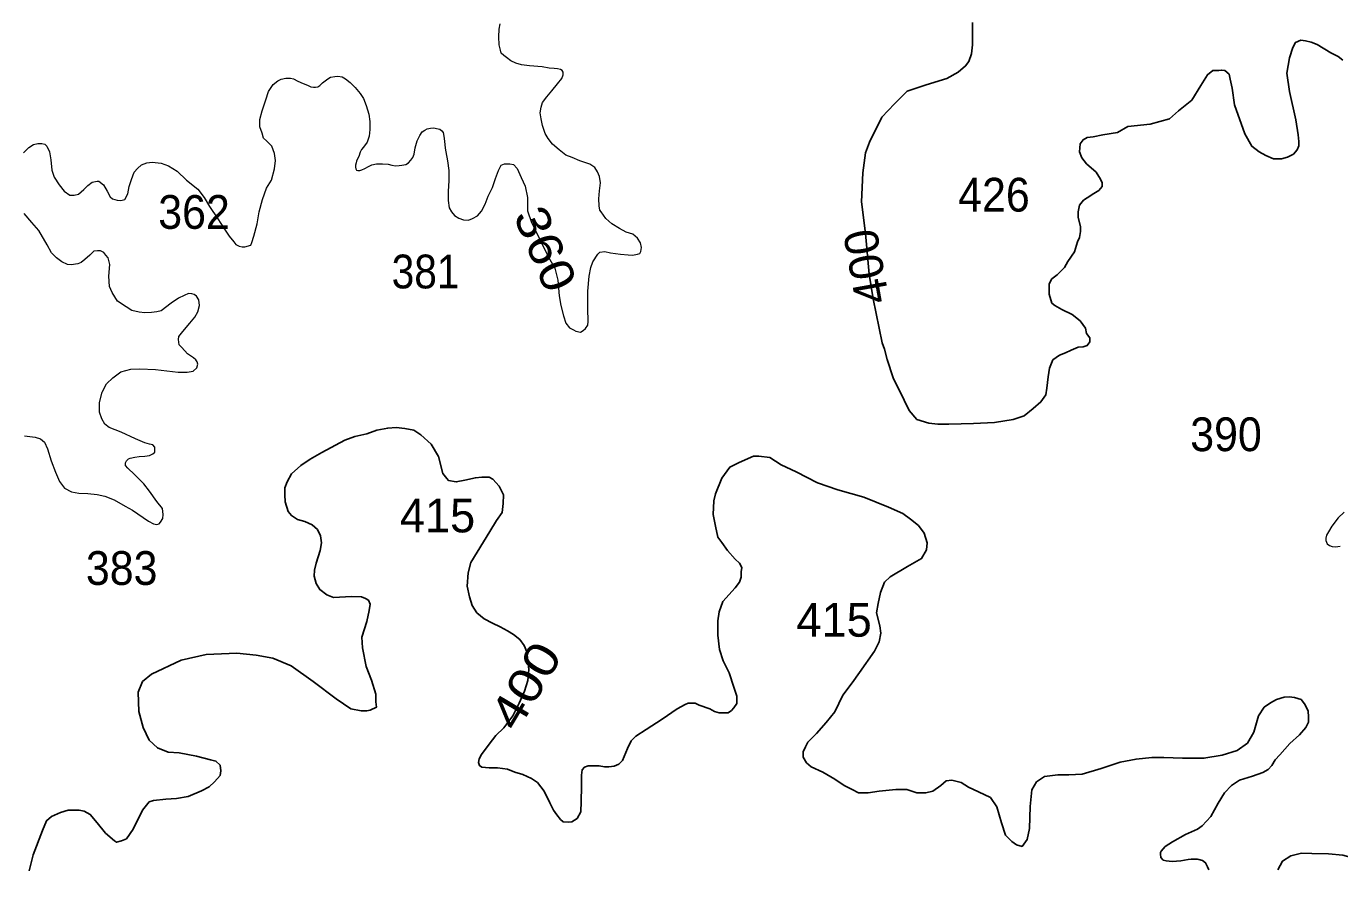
# Model space of a CAD drawing. Extents: x 445.4 to 500, y 8728.7 to 8784.
# Drawn here: x 472.73 to 478.95, y 8728.71 to 8732.71 of the extents above; entities that cross this region are included whole.
import ezdxf
from ezdxf.enums import TextEntityAlignment as Align

# ---------------------------------------------------------------- set-up
doc = ezdxf.new("R2010")
doc.units = 0
doc.header["$LTSCALE"] = 0.064
doc.layers.add('1', color=7, linetype='Continuous', lineweight=25)
doc.layers.add('2', color=7, linetype='Continuous', lineweight=13)
doc.layers.add('21', color=7, linetype='Continuous')
doc.layers.add('61', color=7, linetype='Continuous')

msp = doc.modelspace()

# ---------------------------------------------------------------- linework, layer by layer
at = {"layer": '1'}
for points in [[(476.7866, 8731.2088), (476.7434, 8731.4167), (476.7247, 8731.5347), (476.7078, 8731.7273), (476.689, 8731.8772), (476.6946, 8732.0139), (476.7078, 8732.1091), (476.7266, 8732.1597), (476.7847, 8732.2777), (476.8448, 8732.3414), (476.9049, 8732.4013), (476.995, 8732.4313), (477.0925, 8732.4613), (477.147, 8732.4912), (477.1813, 8732.5206), (477.1963, 8732.5412), (477.2094, 8732.5787), (477.215, 8732.6199), (477.215, 8732.7267)], [(478.9125, 8732.5825), (478.8469, 8732.6224), (478.8184, 8732.6338), (478.7927, 8732.6395), (478.7699, 8732.6423), (478.7442, 8732.6309), (478.7328, 8732.6081), (478.7157, 8732.5597), (478.7043, 8732.4857), (478.7157, 8732.4003), (478.7464, 8732.2651), (478.7578, 8732.1939), (478.7607, 8732.1626), (478.7607, 8732.1426), (478.7521, 8732.1227), (478.735, 8732.1028), (478.7065, 8732.0885), (478.6779, 8732.08), (478.6409, 8732.08), (478.6038, 8732.0971), (478.5724, 8732.1142), (478.5381, 8732.1398), (478.5039, 8732.1996), (478.4554, 8732.3363), (478.444, 8732.416), (478.4354, 8732.4587), (478.4297, 8732.4815), (478.4097, 8732.4986), (478.3955, 8732.5014), (478.3812, 8732.4986), (478.3527, 8732.4986), (478.327, 8732.4787), (478.2956, 8732.4274), (478.2528, 8732.3591), (478.1901, 8732.3078), (478.1473, 8732.2708), (478.056, 8732.2452), (477.9504, 8732.2338), (477.9019, 8732.2053), (477.8321, 8732.1938), (477.7865, 8732.1852), (477.7579, 8732.1824), (477.738, 8732.171), (477.7237, 8732.1511), (477.7208, 8732.114), (477.7323, 8732.0856), (477.7551, 8732.0571), (477.8007, 8732.0172), (477.8207, 8731.984), (477.8292, 8731.9669), (477.8292, 8731.9498), (477.8121, 8731.9299), (477.7893, 8731.9156), (477.7579, 8731.8957), (477.7408, 8731.8843), (477.7208, 8731.8615), (477.7151, 8731.8302), (477.7151, 8731.8046), (477.7265, 8731.759), (477.7265, 8731.7362), (477.7208, 8731.7078), (477.7122, 8731.6878), (477.698, 8731.6394), (477.6666, 8731.5939), (477.6495, 8731.5654), (477.6152, 8731.5312), (477.5896, 8731.5113), (477.5781, 8731.4885), (477.5781, 8731.4401), (477.5896, 8731.3974), (477.6038, 8731.386), (477.6381, 8731.366), (477.6866, 8731.3433), (477.7238, 8731.3131), (477.7495, 8731.2789), (477.7552, 8731.2533), (477.7695, 8731.2333), (477.7695, 8731.2134), (477.758, 8731.1963), (477.7381, 8731.1906), (477.7152, 8731.1878), (477.681, 8731.1735), (477.6553, 8731.1621), (477.6268, 8731.1508), (477.5954, 8731.128), (477.5783, 8731.0881), (477.5726, 8731.0482), (477.5669, 8730.9941), (477.5612, 8730.9628), (477.5384, 8730.9286), (477.5013, 8730.8973), (477.4585, 8730.8631), (477.4071, 8730.8461), (477.3187, 8730.8318), (477.2188, 8730.8261), (477.1018, 8730.8233), (477.0505, 8730.8233), (477.0077, 8730.829), (476.9506, 8730.8461), (476.9135, 8730.8888), (476.8907, 8730.9372)], [(478.9696, 8732.5483), (478.9468, 8732.5654), (478.9125, 8732.5825)], [(476.8907, 8730.9372), (476.8379, 8731.0423), (476.8093, 8731.1306), (476.7979, 8731.179), (476.7866, 8731.2088)], [(472.7448, 8728.708), (472.7639, 8728.784), (472.8067, 8728.8989), (472.8264, 8728.9449), (472.8494, 8728.9646), (472.8922, 8728.9843), (472.9284, 8728.9942), (472.9811, 8728.9942), (473.0041, 8728.9909), (473.0337, 8728.9745), (473.0666, 8728.9351), (473.1061, 8728.8858), (473.1489, 8728.8497), (473.1587, 8728.8431), (473.1818, 8728.8497), (473.2048, 8728.8595), (473.2377, 8728.9055), (473.2805, 8728.9942), (473.3134, 8729.0336), (473.3331, 8729.0402), (473.3924, 8729.0467), (473.4417, 8729.05), (473.4976, 8729.0599), (473.5602, 8729.0861), (473.5964, 8729.1058), (473.6227, 8729.1288), (473.649, 8729.1584), (473.6523, 8729.1814), (473.649, 8729.2076), (473.6293, 8729.2274), (473.6029, 8729.2339), (473.5371, 8729.2503), (473.4549, 8729.2668), (473.4022, 8729.27), (473.3529, 8729.2898), (473.3134, 8729.3259), (473.2843, 8729.387), (473.2645, 8729.4625), (473.2612, 8729.5544), (473.281, 8729.6037), (473.3238, 8729.6398), (473.4652, 8729.7055), (473.5837, 8729.7318), (473.7285, 8729.7384), (473.8206, 8729.7285), (473.8996, 8729.7154), (473.9851, 8729.6792), (474.0904, 8729.6037), (474.199, 8729.5216), (474.2681, 8729.4756), (474.3175, 8729.4658), (474.3438, 8729.4658), (474.3602, 8729.4691), (474.3899, 8729.4822), (474.3866, 8729.5085), (474.3866, 8729.5446), (474.3668, 8729.6103), (474.3405, 8729.676), (474.324, 8729.7646), (474.3208, 8729.8139), (474.3438, 8729.8894), (474.3548, 8729.9405), (474.3596, 8729.9709), (474.3516, 8729.9895), (474.3383, 8729.9975), (474.3196, 8730.0055), (474.2715, 8730.0068), (474.1861, 8730.0029), (474.1554, 8730.0148), (474.122, 8730.0402), (474.1046, 8730.0681), (474.0953, 8730.1028), (474.0966, 8730.1321), (474.1046, 8730.1654), (474.1232, 8730.225), (474.1299, 8730.261), (474.1246, 8730.2943), (474.1099, 8730.325), (474.0859, 8730.3463), (474.0512, 8730.3623), (474.0151, 8730.3716), (473.9871, 8730.3903), (473.971, 8730.4103), (473.9574, 8730.4562), (473.956, 8730.4882), (473.956, 8730.5215), (473.9667, 8730.5508), (473.9867, 8730.5881), (474.0321, 8730.6281), (474.0762, 8730.6574), (474.1309, 8730.6894), (474.2394, 8730.7476), (474.2875, 8730.7649), (474.3449, 8730.7783), (474.3916, 8730.7956), (474.4437, 8730.8049), (474.4838, 8730.8076), (474.5238, 8730.8036), (474.5665, 8730.7956), (474.5999, 8730.7729), (474.6493, 8730.729)], [(474.6493, 8730.729), (474.684, 8730.6703), (474.704, 8730.5904), (474.7241, 8730.5654), (474.7306, 8730.5567), (474.7676, 8730.5502), (474.8089, 8730.5588), (474.859, 8730.5697), (474.8894, 8730.5719), (474.9243, 8730.5719), (474.9417, 8730.5632), (474.9721, 8730.5306), (474.9917, 8730.4893), (474.9896, 8730.4481), (474.9852, 8730.4046), (474.9591, 8730.3677), (474.9264, 8730.3156), (474.837, 8730.1689), (474.824, 8730.119), (474.8196, 8730.056), (474.8305, 8730.006), (474.8436, 8729.9648), (474.8653, 8729.93), (474.9003, 8729.9009), (474.9394, 8729.8813), (474.9764, 8729.864), (475.0113, 8729.8444), (475.0395, 8729.827), (475.07, 8729.8031), (475.0896, 8729.7749), (475.1027, 8729.7445), (475.1115, 8729.6608), (475.1071, 8729.6087), (475.0919, 8729.5588), (475.0658, 8729.5023), (475.0353, 8729.4415), (474.994, 8729.385), (474.9548, 8729.3481), (474.9243, 8729.3068), (474.8871, 8729.2579), (474.8762, 8729.2384), (474.874, 8729.221), (474.8784, 8729.2058), (474.8893, 8729.1993), (474.9241, 8729.1949), (474.9633, 8729.1949), (475.0111, 8729.1884), (475.046, 8729.1754), (475.083, 8729.1645), (475.1243, 8729.145), (475.1526, 8729.1254), (475.1852, 8729.0842), (475.2114, 8729.0299), (475.2288, 8728.9951), (475.2446, 8728.9724), (475.262, 8728.9507), (475.2751, 8728.9398), (475.299, 8728.9376), (475.3164, 8728.9398), (475.3403, 8728.955), (475.3578, 8728.9876), (475.3599, 8729.0354), (475.3621, 8729.107), (475.3621, 8729.1613), (475.3643, 8729.1852), (475.3752, 8729.1983), (475.3926, 8729.2048), (475.4209, 8729.2048), (475.4448, 8729.2048), (475.4709, 8729.2004), (475.4905, 8729.2004), (475.5166, 8729.2026), (475.5384, 8729.2135), (475.5558, 8729.2309), (475.5797, 8729.2873), (475.5975, 8729.3235), (475.6193, 8729.3453), (475.6672, 8729.3778), (475.7433, 8729.4256), (475.8152, 8729.4756), (475.8521, 8729.4951), (475.8674, 8729.5017), (475.9, 8729.5017), (475.9196, 8729.493), (475.9697, 8729.4756), (475.9914, 8729.4626), (476.0132, 8729.456), (476.0371, 8729.456), (476.0567, 8729.456), (476.0719, 8729.4669), (476.0828, 8729.4799), (476.0981, 8729.4995), (476.0981, 8729.5342), (476.0828, 8729.5777), (476.0611, 8729.645), (476.0331, 8729.7025), (476.0157, 8729.7568), (476.007, 8729.8241), (476.007, 8729.8915), (476.0135, 8729.9349), (476.0309, 8729.9827)], [(476.0309, 8729.9827), (476.0897, 8730.0479), (476.1097, 8730.0755), (476.1184, 8730.0994), (476.1184, 8730.1233), (476.1206, 8730.145), (476.1097, 8730.1645), (476.0901, 8730.1841), (476.0531, 8730.2253), (476.027, 8730.2623), (476.0074, 8730.2883), (475.9963, 8730.34), (475.9851, 8730.3961), (475.9888, 8730.4596), (475.9963, 8730.4932), (476.0263, 8730.5679), (476.0637, 8730.6202), (476.1086, 8730.6426), (476.176, 8730.6725), (476.2022, 8730.6725), (476.2546, 8730.665), (476.307, 8730.6314), (476.3781, 8730.5978), (476.4792, 8730.5455), (476.5765, 8730.5119), (476.7, 8730.4782), (476.8161, 8730.4297), (476.8834, 8730.3998), (476.9209, 8730.3736), (476.9583, 8730.3438), (476.9845, 8730.3064), (476.9995, 8730.2616), (476.9957, 8730.2279), (476.9733, 8730.1868), (476.9059, 8730.1495), (476.8235, 8730.1009), (476.7973, 8730.0748), (476.7786, 8730.0262), (476.7674, 8729.9739), (476.7599, 8729.9291), (476.7754, 8729.8678), (476.7791, 8729.8342), (476.7717, 8729.7931), (476.7492, 8729.7482), (476.6781, 8729.6474), (476.6444, 8729.5988), (476.5995, 8729.539), (476.562, 8729.4606), (476.5208, 8729.41), (476.4758, 8729.3577), (476.4347, 8729.3166), (476.4234, 8729.2942), (476.4122, 8729.2717), (476.4122, 8729.2456), (476.4272, 8729.2194), (476.4496, 8729.2008), (476.5058, 8729.1746), (476.5619, 8729.141), (476.6069, 8729.1111), (476.6443, 8729.0924), (476.6742, 8729.0775), (476.7191, 8729.0775), (476.7715, 8729.0849), (476.8502, 8729.0924), (476.9026, 8729.0924), (476.9512, 8729.0775), (476.9924, 8729.0775), (477.0261, 8729.0849), (477.0635, 8729.1111), (477.0897, 8729.1335), (477.1159, 8729.1373), (477.1608, 8729.126), (477.1945, 8729.1036), (477.2432, 8729.0812), (477.2993, 8729.0551), (477.3293, 8729.0102), (477.3517, 8728.9355), (477.3704, 8728.8757), (477.4004, 8728.8459), (477.4228, 8728.8309), (477.449, 8728.8234), (477.4725, 8728.856), (477.4838, 8728.9083), (477.4875, 8729.0129), (477.495, 8729.0913), (477.5175, 8729.1287), (477.5549, 8729.1548), (477.6185, 8729.1623), (477.6709, 8729.1623), (477.7346, 8729.166), (477.8244, 8729.1922), (477.9142, 8729.2221), (477.9891, 8729.237), (478.0639, 8729.2445), (478.1201, 8729.2445), (478.2099, 8729.2408), (478.311, 8729.2408), (478.3971, 8729.2557), (478.4682, 8729.2781), (478.5169, 8729.3117), (478.5468, 8729.364)], [(478.5468, 8729.364), (478.5693, 8729.4425), (478.5964, 8729.4823), (478.6258, 8729.5032), (478.6552, 8729.5186), (478.6916, 8729.5297), (478.714, 8729.5325), (478.7406, 8729.5283), (478.7713, 8729.5186), (478.7881, 8729.499), (478.8049, 8729.4655), (478.8063, 8729.4362), (478.8063, 8729.4124), (478.7937, 8729.3859), (478.7643, 8729.3524), (478.7182, 8729.3105), (478.6706, 8729.2574), (478.6492, 8729.2334), (478.6321, 8729.2068), (478.615, 8729.1878), (478.5902, 8729.1726), (478.5408, 8729.1556), (478.4799, 8729.1366), (478.4418, 8729.1119), (478.4076, 8729.0777), (478.379, 8729.0283), (478.3429, 8728.9656), (478.3029, 8728.9201), (478.2801, 8728.9049), (478.223, 8728.8802), (478.1621, 8728.8441), (478.1277, 8728.8222), (478.1086, 8728.8), (478.1055, 8728.7937), (478.1055, 8728.7857), (478.1071, 8728.7699), (478.1182, 8728.7588), (478.1325, 8728.7556), (478.1611, 8728.7524), (478.1801, 8728.754), (478.2008, 8728.7556), (478.2357, 8728.7604), (478.2516, 8728.7635), (478.2675, 8728.7635), (478.2802, 8728.762), (478.2865, 8728.7604), (478.304, 8728.7572), (478.3183, 8728.7461), (478.3278, 8728.7271), (478.3335, 8728.7123)], [(478.6614, 8728.7126), (478.6828, 8728.7538), (478.7229, 8728.7791), (478.7734, 8728.7917), (478.8218, 8728.7896), (478.9019, 8728.7875), (478.9692, 8728.7812), (479.0345, 8728.7644), (479.0851, 8728.7433), (479.1335, 8728.716), (479.1368, 8728.7129)]]:
    msp.add_lwpolyline(points, dxfattribs=at)
at = {"layer": '2'}
for points in [[(474.9542, 8731.9877), (474.9686, 8732.0248), (474.9801, 8732.0499), (474.997, 8732.0562), (475.0224, 8732.0562), (475.0394, 8732.0541), (475.0563, 8732.0351), (475.0754, 8731.9929), (475.0944, 8731.9506), (475.105, 8731.8978), (475.105, 8731.8344), (475.1244, 8731.7782), (475.1476, 8731.7317), (475.1751, 8731.6747), (475.2111, 8731.6029), (475.2344, 8731.5627), (475.2492, 8731.5057), (475.2556, 8731.4318), (475.2641, 8731.386), (475.2768, 8731.3374), (475.2874, 8731.3015), (475.3043, 8731.2804), (475.3234, 8731.2698), (475.3339, 8731.2635), (475.3572, 8731.2593), (475.3699, 8731.2677), (475.3805, 8731.2762), (475.3911, 8731.2931), (475.3932, 8731.31), (475.3911, 8731.3712), (475.3911, 8731.4536), (475.3974, 8731.5254), (475.4059, 8731.5656), (475.4144, 8731.593), (475.4381, 8731.6283), (475.4487, 8731.6388), (475.472, 8731.6409), (475.4995, 8731.6346), (475.5461, 8731.6283), (475.5821, 8731.6261), (475.6032, 8731.624), (475.6265, 8731.6283), (475.6371, 8731.6325), (475.6434, 8731.6409), (475.6456, 8731.6599), (475.6413, 8731.6832), (475.6265, 8731.7043), (475.6053, 8731.7233), (475.5736, 8731.7339), (475.5419, 8731.7508), (475.5059, 8731.7719), (475.4762, 8731.7972), (475.4551, 8731.8289), (475.4487, 8731.8374), (475.4444, 8731.8582), (475.443, 8731.8916), (475.447, 8731.929), (475.4511, 8731.9664), (475.447, 8731.9972), (475.4377, 8732.0186), (475.4243, 8732.0399), (475.4015, 8732.0546), (475.3533, 8732.0707), (475.3172, 8732.0867), (475.2877, 8732.0974), (475.2556, 8732.1228), (475.2248, 8732.1495), (475.2034, 8732.1776), (475.19, 8732.2003), (475.1764, 8732.2385), (475.1697, 8732.2693), (475.1657, 8732.2987), (475.1697, 8732.3254), (475.1764, 8732.3481), (475.1965, 8732.3749), (475.2206, 8732.4029), (475.2474, 8732.4363), (475.2688, 8732.4617), (475.2746, 8732.4778), (475.2739, 8732.491), (475.2695, 8732.4983), (475.2614, 8732.5035), (475.2481, 8732.5071), (475.2327, 8732.5086), (475.2077, 8732.5108), (475.1745, 8732.5167), (475.115, 8732.5204), (475.0767, 8732.5262), (475.0502, 8732.5343), (475.0267, 8732.5446), (475.0068, 8732.56), (474.9928, 8732.5696), (474.9801, 8732.581), (474.9772, 8732.595), (474.9706, 8732.6214), (474.9691, 8732.6581), (474.9713, 8732.6941), (474.9764, 8732.7198)], [(473.8544, 8732.1779), (473.8478, 8732.202), (473.8378, 8732.2321), (473.8378, 8732.2671), (473.8478, 8732.3072), (473.8654, 8732.3599), (473.878, 8732.4), (473.9005, 8732.4325), (473.9231, 8732.4501), (473.9377, 8732.4585), (473.9608, 8732.4626), (473.9823, 8732.4626), (473.9972, 8732.4593), (474.017, 8732.4486), (474.0418, 8732.4378), (474.0625, 8732.4296), (474.0782, 8732.4222), (474.0914, 8732.4197), (474.1005, 8732.4205), (474.112, 8732.4213), (474.1219, 8732.4279), (474.1343, 8732.4411), (474.1591, 8732.4601), (474.1723, 8732.4667), (474.193, 8732.47), (474.207, 8732.4717), (474.2269, 8732.4684), (474.2426, 8732.4601), (474.2649, 8732.4428), (474.2897, 8732.4181), (474.312, 8732.3908), (474.3285, 8732.3661), (474.3409, 8732.3339), (474.3539, 8732.2921), (474.3589, 8732.2573), (474.3589, 8732.2192), (474.3556, 8732.1877), (474.3456, 8732.1595), (474.329, 8732.1363), (474.3184, 8732.1241), (474.3126, 8732.1115), (474.3067, 8732.0922), (474.2999, 8732.0805), (474.2959, 8732.0701), (474.2941, 8732.0611), (474.2905, 8732.0508), (474.2905, 8732.0413), (474.2914, 8732.0336), (474.2954, 8732.0273), (474.3017, 8732.0255), (474.3112, 8732.0255), (474.3202, 8732.0287), (474.3351, 8732.0354), (474.3514, 8732.0449), (474.3676, 8732.0517), (474.3897, 8732.0575), (474.4185, 8732.0571), (474.4456, 8732.0548), (474.4627, 8732.0508), (474.4808, 8732.0481), (474.497, 8732.0494), (474.5096, 8732.0499), (474.529, 8732.0544), (474.5412, 8732.062), (474.5527, 8732.0735), (474.5626, 8732.0872), (474.5687, 8732.1024), (474.5733, 8732.1322), (474.5832, 8732.1658), (474.5955, 8732.1917), (474.6062, 8732.2077), (474.6192, 8732.2166), (474.6307, 8732.2219), (474.6452, 8732.2265), (474.6613, 8732.2272), (474.675, 8732.225), (474.6896, 8732.2211), (474.7003, 8732.2135), (474.7064, 8732.2051), (474.7094, 8732.1883), (474.7125, 8732.1639), (474.7156, 8732.1311), (474.7186, 8732.1136), (474.7264, 8732.0711), (474.7336, 8732.0248), (474.7321, 8731.9762), (474.7293, 8731.9276), (474.7293, 8731.8833), (474.735, 8731.8489), (474.745, 8731.8289), (474.7594, 8731.8118), (474.7809, 8731.7989), (474.8024, 8731.7917), (474.8253, 8731.7903), (474.8453, 8731.7975), (474.8683, 8731.8103), (474.8869, 8731.8332), (474.9055, 8731.8661), (474.9199, 8731.9033), (474.9399, 8731.9448), (474.9542, 8731.9877)], [(472.7176, 8732.1087), (472.7427, 8732.1338), (472.7645, 8732.1488), (472.7846, 8732.1538), (472.8046, 8732.1538), (472.818, 8732.1505), (472.8281, 8732.1405), (472.8398, 8732.1137), (472.8465, 8732.0753), (472.8515, 8732.0269), (472.8632, 8731.9934), (472.8867, 8731.9567), (472.9101, 8731.9266), (472.9369, 8731.9082), (472.957, 8731.9082), (472.9787, 8731.9133), (473.0038, 8731.935), (473.0222, 8731.955), (473.0423, 8731.9701), (473.0658, 8731.9751), (473.0741, 8731.9751), (473.0959, 8731.9567), (473.1143, 8731.9266), (473.1277, 8731.8999), (473.1394, 8731.8915), (473.1612, 8731.8849), (473.1779, 8731.8832), (473.198, 8731.8882), (473.2114, 8731.9149), (473.2181, 8731.95), (473.2298, 8731.9834), (473.2415, 8732.0168), (473.2583, 8732.0352), (473.2767, 8732.0519), (473.3018, 8732.0619), (473.3269, 8732.0653), (473.3698, 8732.0601), (473.405, 8732.0476), (473.4451, 8732.0225), (473.4903, 8731.9799), (473.5431, 8731.9373), (473.5732, 8731.8972), (473.5983, 8731.8546), (473.6385, 8731.797), (473.6661, 8731.7519), (473.6912, 8731.7143), (473.7138, 8731.6867), (473.7238, 8731.6742), (473.7389, 8731.6667), (473.754, 8731.6642), (473.7665, 8731.6642), (473.7941, 8731.6717), (473.7992, 8731.6842), (473.8092, 8731.7143), (473.8243, 8731.7719), (473.8343, 8731.8296), (473.8494, 8731.8872), (473.8695, 8731.9423), (473.8921, 8731.9799), (473.9071, 8732.0326), (473.9122, 8732.0727), (473.9071, 8732.1052), (473.8946, 8732.1403), (473.8695, 8732.1654), (473.8544, 8732.1779)], [(473.3485, 8731.3553), (473.3241, 8731.3522), (473.292, 8731.3507), (473.266, 8731.3538), (473.2309, 8731.3614), (473.2035, 8731.3797), (473.1622, 8731.4056), (473.1378, 8731.4467), (473.1256, 8731.4757), (473.1225, 8731.5244), (473.1271, 8731.5793), (473.1193, 8731.6108), (473.107, 8731.6245), (473.0979, 8731.6367), (473.0826, 8731.6443), (473.0674, 8731.6443), (473.0506, 8731.6428), (473.0322, 8731.6245), (473.0078, 8731.6031), (472.991, 8731.5894), (472.9742, 8731.5833), (472.9437, 8731.5788), (472.9254, 8731.5803), (472.8994, 8731.5925), (472.8735, 8731.6123), (472.8506, 8731.6351), (472.8292, 8731.6732), (472.7895, 8731.7403), (472.7561, 8731.7796), (472.721, 8731.8214)], [(472.7222, 8730.769), (472.7723, 8730.7623), (472.7973, 8730.754), (472.8174, 8730.739), (472.8307, 8730.7073), (472.8491, 8730.6506), (472.8692, 8730.5956), (472.8875, 8730.5522), (472.9109, 8730.5205), (472.9443, 8730.5022), (472.9794, 8730.4972), (473.0228, 8730.4955), (473.0663, 8730.4905), (473.103, 8730.4822), (473.1465, 8730.4655), (473.1999, 8730.4355), (473.2333, 8730.4155), (473.2839, 8730.3816), (473.309, 8730.3639), (473.3326, 8730.3506), (473.3489, 8730.3477), (473.3607, 8730.3521), (473.3666, 8730.3595), (473.3769, 8730.3771), (473.3784, 8730.3963), (473.3754, 8730.4243), (473.3489, 8730.4567), (473.3149, 8730.5068), (473.2883, 8730.5407), (473.244, 8730.5849), (473.2117, 8730.615), (473.2009, 8730.6283), (473.2, 8730.6408), (473.2059, 8730.6491), (473.2151, 8730.66), (473.2234, 8730.6625), (473.2442, 8730.6666), (473.2659, 8730.6708), (473.2926, 8730.6716), (473.3143, 8730.6758), (473.3309, 8730.6833), (473.3393, 8730.6916), (473.3401, 8730.7041), (473.3393, 8730.714), (473.3309, 8730.7257), (473.3143, 8730.7282), (473.2926, 8730.7357), (473.2484, 8730.754), (473.1809, 8730.7856), (473.1237, 8730.807), (473.1024, 8730.8238), (473.0886, 8730.8482), (473.0779, 8730.8802), (473.0779, 8730.9259), (473.0901, 8730.9746), (473.11, 8731.0143), (473.1405, 8731.0432), (473.1787, 8731.0722), (473.226, 8731.0843), (473.2687, 8731.0859), (473.3435, 8731.0828), (473.4504, 8731.0706), (473.4931, 8731.0706), (473.5206, 8731.0752), (473.5389, 8731.0904), (473.5435, 8731.1072), (473.5405, 8731.1194), (473.5344, 8731.1285), (473.5222, 8731.1377), (473.4947, 8731.156), (473.4672, 8731.1864), (473.4553, 8731.1999), (473.4523, 8731.2243), (473.4538, 8731.2395), (473.4721, 8731.2624), (473.5057, 8731.302), (473.5286, 8731.3309), (473.5439, 8731.3553), (473.5515, 8731.3858), (473.5485, 8731.4132), (473.5378, 8731.43), (473.5256, 8731.4376), (473.5149, 8731.4406), (473.4996, 8731.4421), (473.4782, 8731.433), (473.4523, 8731.4208), (473.4172, 8731.3964), (473.3699, 8731.3599), (473.3485, 8731.3553)], [(478.9749, 8730.4059), (478.9471, 8730.3794), (478.9176, 8730.3402), (478.9017, 8730.3137), (478.8924, 8730.2977), (478.8884, 8730.2832), (478.8884, 8730.2726), (478.895, 8730.2566), (478.9057, 8730.2487), (478.919, 8730.2434), (478.9349, 8730.2421), (478.9562, 8730.246)]]:
    msp.add_lwpolyline(points, dxfattribs=at)

# ---------------------------------------------------------------- texts
at = {"layer": '21'}
for s, width, p in [('426', 0.95, (477.1464, 8731.8307)), ('362', 0.95, (473.3559, 8731.7489)), ('381', 0.9, (474.462, 8731.4668)), ('390', 0.95, (478.2459, 8730.6956)), ('383', 0.95, (473.013, 8730.062))]:
    msp.add_text(s, height=0.16, dxfattribs=dict(at, width=width)).set_placement(p)
for p in [(474.5007, 8730.3109), (476.3799, 8729.8167)]:
    msp.add_text('415', height=0.16, dxfattribs=at).set_placement(p)
at = {"layer": '61'}
for s, rotation, width, p in [('360', 293.047, 1.15, (475.117, 8731.623)), ('400', 59.243, 1.2, (475.1654, 8729.5442))]:
    msp.add_text(s, height=0.16, rotation=rotation, dxfattribs=dict(at, width=width)).set_placement(p, align=Align.CENTER)
msp.add_text('400', height=0.16, rotation=100.125, dxfattribs=at).set_placement((476.7896, 8731.5828), align=Align.CENTER)

doc.saveas('drawing.dxf')
